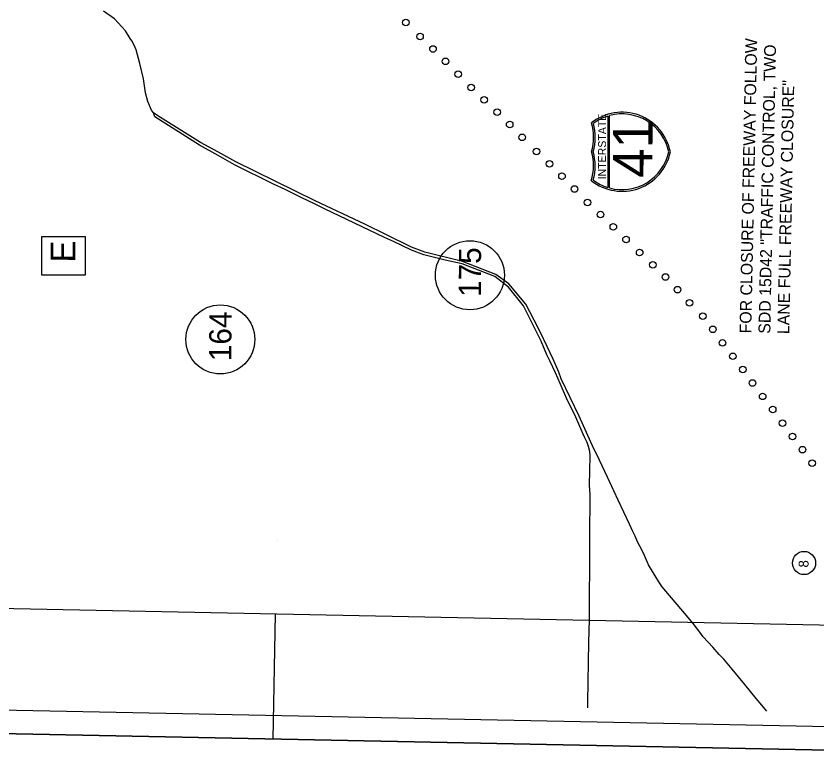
# Model space of a CAD drawing. Extents: x 311409 to 379449, y 121539 to 224848.
# Drawn here: x 336594 to 360929, y 121539 to 144161 of the extents above; entities that cross this region are included whole.
import ezdxf

# ---------------------------------------------------------------- set-up
doc = ezdxf.new("R2010")
doc.units = 0
for name, color, linetype in [('CA-TEXT', 7, 'Continuous'), ('CE-TOPO-CONC-SLAB', 7, 'Continuous'), ('Level 1', 7, 'Continuous'), ('Level 58', 7, 'Continuous'), ('P_RDWY_Text', 7, 'Continuous'), ('PLT_Sheet_Border', 7, 'Continuous'), ('PLT_Sheet_Info', 7, 'Continuous')]:
    doc.layers.add(name, color=color, linetype=linetype)

msp = doc.modelspace()

# ---------------------------------------------------------------- linework, layer by layer
at = {"layer": 'CA-TEXT'}
for p, q in [((354578, 141123), (354573, 138954)), ((354623, 138940), (354628, 141138)), ((338020, 136903), (338020, 136903)), ((350385, 136290), (350385, 136290)), ((342802, 134339), (342802, 134339))]:
    msp.add_line(p, q, dxfattribs=at)
msp.add_lwpolyline([(338690, 136287), (337378, 136292), (337383, 137470), (338695, 137465)], close=True, dxfattribs=at)
for centre, radius in [((350385, 136290), 1048), ((342802, 134339), 1048), ((360536, 127551), 352)]:
    msp.add_circle(centre, radius, dxfattribs=at)
for centre, radius, start, end in [((355005, 139738), 1500, 11.3832, 128.1773), ((355005, 139738), 1450, 11.7868, 105.0434), ((352643, 140482), 1500, 342.8553, 16.8422), ((355005, 139738), 1450, 107.1012, 126.8422), ((352643, 140482), 1550, 343.4192, 15.5586), ((352640, 139606), 1500, 342.8502, 16.8372), ((355006, 140338), 1500, 231.5152, 348.3093), ((352640, 139606), 1550, 344.1339, 16.2733), ((355006, 140338), 1450, 254.649, 347.9057), ((355006, 140338), 1450, 232.8503, 252.5912)]:
    msp.add_arc(centre, radius, start, end, dxfattribs=at)
at = {"layer": 'CE-TOPO-CONC-SLAB'}
for centre in [(348437, 143966), (348869, 143536), (349263, 143160), (349645, 142785), (350026, 142396), (350419, 141989), (350817, 141618), (351211, 141242), (351593, 140867), (351974, 140478), (352406, 140048), (352800, 139672), (353182, 139297), (353563, 138908), (353956, 138501), (354354, 138130), (354741, 137760), (355127, 137375), (355541, 136976), (355939, 136605), (356326, 136235), (356691, 135851), (357055, 135453), (357463, 135045), (357767, 134646), (358062, 134233), (358371, 133828), (358675, 133429), (358970, 133016), (359279, 132611), (359583, 132211), (359879, 131797), (360189, 131392), (360492, 130993), (360781, 130585)]:
    msp.add_circle(centre, 100, dxfattribs=at)
at = {"layer": 'Level 1'}
msp.add_line((359082, 123437), (359089, 123431), dxfattribs=at)
for points in [[(340066, 143483), (339923, 143711), (339582, 144071), (339253, 144311)], [(340358, 142714), (340243, 143134), (340182, 143278), (340108, 143404), (340066, 143483)], [(340466, 142250), (340358, 142714)], [(340776, 141222), (340714, 141304), (340597, 141568), (340525, 141825), (340466, 142250)], [(342197, 140321), (340900, 141134), (340776, 141222)], [(343270, 139728), (342722, 140036), (342197, 140321)], [(347853, 137515), (347187, 137839), (345680, 138553), (343270, 139728)], [(350160, 136706), (349012, 136985), (348607, 137139), (347853, 137515)], [(351176, 136316), (350160, 136706)], [(352087, 135407), (351567, 136031), (351176, 136316)], [(352640, 134321), (352622, 134359), (352462, 134691), (352087, 135407)], [(353161, 133148), (353081, 133348), (352910, 133737), (352640, 134321)], [(353707, 132011), (353161, 133148)], [(354762, 129739), (354566, 130160), (354240, 130850), (354154, 131020), (353707, 132011)], [(355807, 127497), (355688, 127775), (355615, 127932), (355479, 128195), (355406, 128365), (355338, 128503), (355228, 128735), (354891, 129463), (354762, 129739)], [(359089, 123431), (359082, 123437), (358742, 123859), (358352, 124325), (358099, 124628), (357962, 124773), (357764, 124999), (357473, 125308), (357374, 125447), (357170, 125717), (356855, 126089), (356453, 126561), (356230, 126832), (356125, 126983), (355903, 127341), (355807, 127497)], [(359408, 123047), (359255, 123236), (359082, 123437)]]:
    msp.add_lwpolyline(points, dxfattribs=at)
at = {"layer": 'Level 58'}
for points in [[(342164, 140243), (340812, 141097), (340776, 141222)], [(343227, 139643), (342734, 139923), (342164, 140243)], [(347790, 137440), (345971, 138307), (345666, 138459), (345274, 138644), (344770, 138892), (344415, 139058), (343227, 139643)], [(350153, 136637), (349635, 136748), (348986, 136911), (348606, 137051), (348058, 137313), (347790, 137440)], [(351138, 136254), (350153, 136637)], [(352012, 135358), (351554, 135931), (351138, 136254)], [(352546, 134284), (352012, 135358)], [(353122, 133006), (352981, 133324), (352809, 133695), (352723, 133877), (352546, 134284)], [(353607, 131975), (353318, 132559), (353122, 133006)], [(354040, 130802), (354029, 130940), (353992, 131084), (353944, 131209), (353864, 131372), (353754, 131630), (353607, 131975)], [(354019, 129915), (354040, 130802)], [(354030, 128327), (354041, 129621), (354019, 129915)], [(354019, 125821), (354028, 128158), (354030, 128327)], [(353971, 123321), (354000, 125152), (354019, 125821)], [(353967, 123157), (353971, 123321)]]:
    msp.add_lwpolyline(points, dxfattribs=at)
at = {"layer": 'P_RDWY_Text'}
msp.add_lwpolyline([(311409, 122868), (313463, 224848), (379449, 223519), (377396, 121539)], close=True, dxfattribs=at)
at = {"layer": 'PLT_Sheet_Border'}
for points in [[(377396, 121539), (379449, 223519), (313463, 224848), (311409, 122868)], [(375910, 122290), (377910, 221569), (314923, 222838), (312923, 123558)]]:
    msp.add_lwpolyline(points, close=True, dxfattribs=at)
at = {"layer": 'PLT_Sheet_Info'}
for p, q in [((344524, 128248), (344524, 128248)), ((374473, 125394), (314485, 126602)), ((344402, 122204), (344479, 125998)), ((345902, 122174), (342903, 122234))]:
    msp.add_line(p, q, dxfattribs=at)

# ---------------------------------------------------------------- texts
at = {"layer": 'CA-TEXT'}
for s, height, rotation, p in [('FOR CLOSURE OF FREEWAY FOLLOW', 360, 88.8468, (358934, 134521)), ('SDD 15D42 "TRAFFIC CONTROL, TWO', 360, 88.8468, (359510, 134510)), ('LANE FULL FREEWAY CLOSURE"', 360, 88.8468, (360086, 134498)), ('INTERSTATE', 239.9, 89.8462, (354517, 139199)), ('41', 1199.7, 89.8462, (355929, 139249)), ('E', 750, 89.767, (338394, 136674)), ('175', 675, 89.767, (350720, 135630)), ('164', 675, 89.767, (343136, 133679)), ('8', 300, 88.8468, (360671, 127411))]:
    msp.add_text(s, height=height, rotation=rotation, dxfattribs=at).set_placement(p)

doc.saveas('drawing.dxf')
